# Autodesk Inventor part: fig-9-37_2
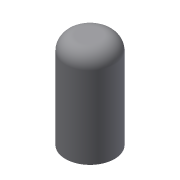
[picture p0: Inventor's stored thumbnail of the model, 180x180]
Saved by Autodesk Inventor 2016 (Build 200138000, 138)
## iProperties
Created: 2013-03
Part Number: fig-9-37_2
Material: Generic
Document SubType Name: Modeling
Designer: CADCIM
Density: 1 g/cm^3
Appearance: Default
Author: CADCIM
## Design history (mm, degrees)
sketch "Sketch1"
  geometry: C1 r 9 at (0, 0); 1 further point
  constraints: 1 centre point, 1 coincident
  dimensions: "d0" = 18 diameter of C1
extrude "Extrusion1" new body sketch "Sketch1" distance "d2" = 35; taper "d3" = 0 deg
fillet "Fillet1" dims "d4" = 5
body "Solid1"
